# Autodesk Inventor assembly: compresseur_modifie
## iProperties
Shininess: 41.0
Length Units: 11269
Angle Units: 11279
Time Units: 11290
Mass Units: 11283
Length Display Precision: 3
Angle Display Precision: 2
Created: 2002-11
Part Number: compresseur_modifie
Document SubType Name: Assemblage
Designer: poste-2
Density: 0.0
Volumn: 0.0
Area: 0.0
PropertySet Name: Model Information
Control State: 0
Master: False
Checked Out: False
Author: poste-2
